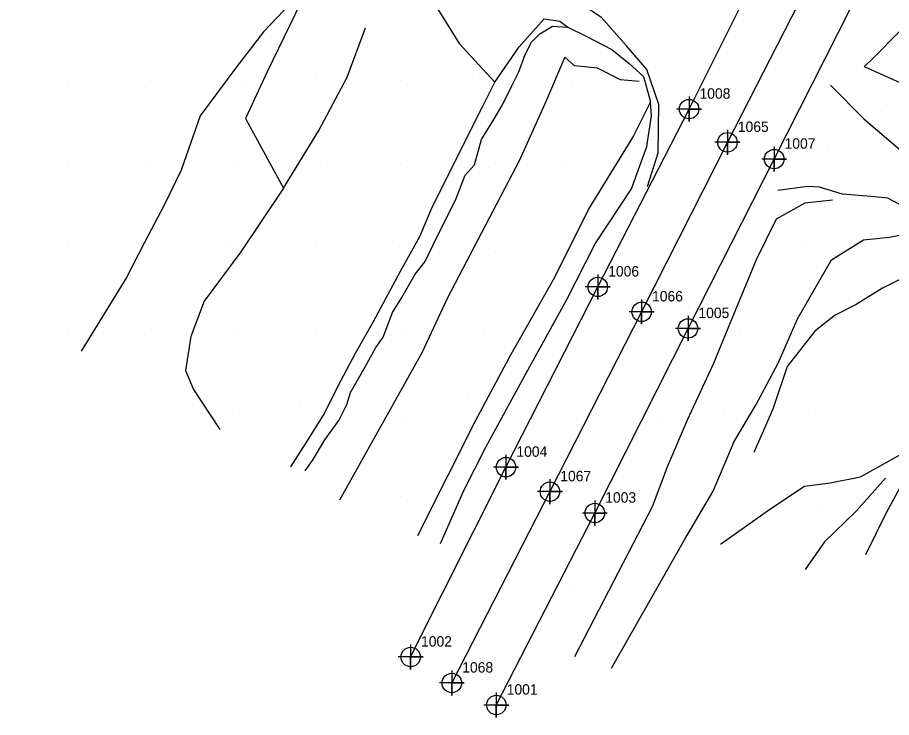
# Model space of a CAD drawing. Extents: x 2062781 to 2066835, y 358981 to 366501.
# Drawn here: x 2063191.9 to 2063402.2, y 359933.1 to 360101.4 of the extents above; entities that cross this region are included whole.
import ezdxf

# ---------------------------------------------------------------- set-up
doc = ezdxf.new("R2010")
doc.units = 0
for name, color, linetype in [('Exist DTM Crownline', 7, 'Continuous'), ('Exist DTM Crownline Cogo Number', 7, 'Continuous'), ('Exist DTM Crownline Cogo Point CELL', 7, 'Continuous'), ('Exist Roads EOP', 7, 'Continuous'), ('Exist Roads EOP Cogo Number', 7, 'Continuous'), ('Exist Roads EOP Cogo Point CELL', 7, 'Continuous'), ('PH Exist DTM Breakline', 7, 'Continuous'), ('PH Exist DTM Point', 7, 'Continuous')]:
    doc.layers.add(name, color=color, linetype=linetype)

msp = doc.modelspace()

# ---------------------------------------------------------------- linework, layer by layer
at = {"layer": 'Exist DTM Crownline'}
msp.add_lwpolyline([(2063750.55, 360833.69), (2063727.84, 360789.3), (2063705.93, 360746.41), (2063683.92, 360702.88), (2063663.24, 360662.2), (2063641.44, 360619.31), (2063619.27, 360575.63), (2063598.51, 360534.74), (2063576.26, 360491.01), (2063554.11, 360448.07), (2063531.69, 360403.69), (2063510.6, 360362.17), (2063489.74, 360321.58), (2063468.62, 360279.83), (2063447.14, 360237.46), (2063426.34, 360196.56), (2063406.83, 360158.2), (2063384.9, 360114.87), (2063362.69, 360071.39), (2063342.05, 360030.63), (2063319.97, 359987.39), (2063296.38, 359941.39)], dxfattribs=at)
at = {"layer": 'Exist DTM Crownline Cogo Point CELL'}
for points in [[(2063362.69, 360074.39), (2063362.69, 360068.39), (2063362.69, 360071.39), (2063365.69, 360071.39), (2063359.69, 360071.39)], [(2063362.69, 360074.39), (2063362.69, 360068.39), (2063362.69, 360071.39), (2063365.69, 360071.39), (2063359.69, 360071.39)], [(2063362.69, 360074.39), (2063362.69, 360068.39), (2063362.69, 360071.39), (2063365.69, 360071.39), (2063359.69, 360071.39)], [(2063342.05, 360033.63), (2063342.05, 360027.63), (2063342.05, 360030.63), (2063345.05, 360030.63), (2063339.05, 360030.63)], [(2063342.05, 360033.63), (2063342.05, 360027.63), (2063342.05, 360030.63), (2063345.05, 360030.63), (2063339.05, 360030.63)], [(2063342.05, 360033.63), (2063342.05, 360027.63), (2063342.05, 360030.63), (2063345.05, 360030.63), (2063339.05, 360030.63)], [(2063319.97, 359990.39), (2063319.97, 359984.39), (2063319.97, 359987.39), (2063322.97, 359987.39), (2063316.97, 359987.39)], [(2063319.97, 359990.39), (2063319.97, 359984.39), (2063319.97, 359987.39), (2063322.97, 359987.39), (2063316.97, 359987.39)], [(2063319.97, 359990.39), (2063319.97, 359984.39), (2063319.97, 359987.39), (2063322.97, 359987.39), (2063316.97, 359987.39)], [(2063296.38, 359944.39), (2063296.38, 359938.39), (2063296.38, 359941.39), (2063299.38, 359941.39), (2063293.38, 359941.39)], [(2063296.38, 359944.39), (2063296.38, 359938.39), (2063296.38, 359941.39), (2063299.38, 359941.39), (2063293.38, 359941.39)], [(2063296.38, 359944.39), (2063296.38, 359938.39), (2063296.38, 359941.39), (2063299.38, 359941.39), (2063293.38, 359941.39)]]:
    msp.add_lwpolyline(points, dxfattribs=at)
for centre in [(2063362.69, 360071.39), (2063362.69, 360071.39), (2063362.69, 360071.39), (2063342.05, 360030.63), (2063342.05, 360030.63), (2063342.05, 360030.63), (2063319.97, 359987.39), (2063319.97, 359987.39), (2063319.97, 359987.39), (2063296.38, 359941.39), (2063296.38, 359941.39), (2063296.38, 359941.39)]:
    msp.add_circle(centre, 2.34, dxfattribs=at)
at = {"layer": 'Exist Roads EOP'}
for points in [[(2063286.47, 359947.64), (2063309.41, 359993.28), (2063331.5, 360036.62), (2063353.47, 360079.37), (2063374.09, 360120.61), (2063394.89, 360165.38), (2063417.4, 360208.71), (2063436.23, 360246.03), (2063449.27, 360270.89), (2063451.38, 360272.28), (2063457.84, 360285.06), (2063479.58, 360327.99), (2063500.63, 360369.12), (2063521.45, 360410.21), (2063543.5, 360453.45), (2063565.77, 360497.25), (2063587.25, 360539.79), (2063609.2, 360582.5), (2063630.76, 360625.39), (2063652.41, 360668.3), (2063674.4, 360710.54), (2063695.41, 360752.05), (2063717.28, 360794.95), (2063739.23, 360837.72)], [(2063307.08, 359936.09), (2063330.79, 359982.25), (2063353.21, 360026.63), (2063373.94, 360067.35), (2063395.33, 360109.66), (2063417.3, 360152.86), (2063438.53, 360194.57), (2063458.78, 360234.01), (2063479.37, 360275.02), (2063500.83, 360316.36), (2063521.71, 360358), (2063542.56, 360398.65), (2063564.98, 360442.66), (2063586.95, 360486.19), (2063608.7, 360528.89), (2063630.33, 360571.32), (2063652.02, 360613.69), (2063674.28, 360656.66), (2063695.45, 360699.25), (2063716.63, 360740.88), (2063738.76, 360783.94), (2063760.61, 360827.22)]]:
    msp.add_lwpolyline(points, dxfattribs=at)
at = {"layer": 'Exist Roads EOP Cogo Point CELL'}
for points in [[(2063353.47, 360082.37), (2063353.47, 360076.37), (2063353.47, 360079.37), (2063356.47, 360079.37), (2063350.47, 360079.37)], [(2063353.47, 360082.37), (2063353.47, 360076.37), (2063353.47, 360079.37), (2063356.47, 360079.37), (2063350.47, 360079.37)], [(2063353.47, 360082.37), (2063353.47, 360076.37), (2063353.47, 360079.37), (2063356.47, 360079.37), (2063350.47, 360079.37)], [(2063373.94, 360070.35), (2063373.94, 360064.35), (2063373.94, 360067.35), (2063376.94, 360067.35), (2063370.94, 360067.35)], [(2063373.94, 360070.35), (2063373.94, 360064.35), (2063373.94, 360067.35), (2063376.94, 360067.35), (2063370.94, 360067.35)], [(2063373.94, 360070.35), (2063373.94, 360064.35), (2063373.94, 360067.35), (2063376.94, 360067.35), (2063370.94, 360067.35)], [(2063331.5, 360039.62), (2063331.5, 360033.62), (2063331.5, 360036.62), (2063334.5, 360036.62), (2063328.5, 360036.62)], [(2063331.5, 360039.62), (2063331.5, 360033.62), (2063331.5, 360036.62), (2063334.5, 360036.62), (2063328.5, 360036.62)], [(2063331.5, 360039.62), (2063331.5, 360033.62), (2063331.5, 360036.62), (2063334.5, 360036.62), (2063328.5, 360036.62)], [(2063353.21, 360029.63), (2063353.21, 360023.63), (2063353.21, 360026.63), (2063356.21, 360026.63), (2063350.21, 360026.63)], [(2063353.21, 360029.63), (2063353.21, 360023.63), (2063353.21, 360026.63), (2063356.21, 360026.63), (2063350.21, 360026.63)], [(2063353.21, 360029.63), (2063353.21, 360023.63), (2063353.21, 360026.63), (2063356.21, 360026.63), (2063350.21, 360026.63)], [(2063309.41, 359996.28), (2063309.41, 359990.28), (2063309.41, 359993.28), (2063312.41, 359993.28), (2063306.41, 359993.28)], [(2063309.41, 359996.28), (2063309.41, 359990.28), (2063309.41, 359993.28), (2063312.41, 359993.28), (2063306.41, 359993.28)], [(2063309.41, 359996.28), (2063309.41, 359990.28), (2063309.41, 359993.28), (2063312.41, 359993.28), (2063306.41, 359993.28)], [(2063330.79, 359985.25), (2063330.79, 359979.25), (2063330.79, 359982.25), (2063333.79, 359982.25), (2063327.79, 359982.25)], [(2063330.79, 359985.25), (2063330.79, 359979.25), (2063330.79, 359982.25), (2063333.79, 359982.25), (2063327.79, 359982.25)], [(2063330.79, 359985.25), (2063330.79, 359979.25), (2063330.79, 359982.25), (2063333.79, 359982.25), (2063327.79, 359982.25)], [(2063286.47, 359950.64), (2063286.47, 359944.64), (2063286.47, 359947.64), (2063289.47, 359947.64), (2063283.47, 359947.64)], [(2063286.47, 359950.64), (2063286.47, 359944.64), (2063286.47, 359947.64), (2063289.47, 359947.64), (2063283.47, 359947.64)], [(2063286.47, 359950.64), (2063286.47, 359944.64), (2063286.47, 359947.64), (2063289.47, 359947.64), (2063283.47, 359947.64)], [(2063307.08, 359939.09), (2063307.08, 359933.09), (2063307.08, 359936.09), (2063310.08, 359936.09), (2063304.08, 359936.09)], [(2063307.08, 359939.09), (2063307.08, 359933.09), (2063307.08, 359936.09), (2063310.08, 359936.09), (2063304.08, 359936.09)], [(2063307.08, 359939.09), (2063307.08, 359933.09), (2063307.08, 359936.09), (2063310.08, 359936.09), (2063304.08, 359936.09)]]:
    msp.add_lwpolyline(points, dxfattribs=at)
for centre in [(2063353.47, 360079.37), (2063353.47, 360079.37), (2063353.47, 360079.37), (2063373.94, 360067.35), (2063373.94, 360067.35), (2063373.94, 360067.35), (2063331.5, 360036.62), (2063331.5, 360036.62), (2063331.5, 360036.62), (2063353.21, 360026.63), (2063353.21, 360026.63), (2063353.21, 360026.63), (2063309.41, 359993.28), (2063309.41, 359993.28), (2063309.41, 359993.28), (2063330.79, 359982.25), (2063330.79, 359982.25), (2063330.79, 359982.25), (2063286.47, 359947.64), (2063286.47, 359947.64), (2063286.47, 359947.64), (2063307.08, 359936.09), (2063307.08, 359936.09), (2063307.08, 359936.09)]:
    msp.add_circle(centre, 2.34, dxfattribs=at)
at = {"layer": 'PH Exist DTM Breakline'}
for points in [[(2063519.4, 360266.45), (2063512.25, 360275.25), (2063507.51, 360283.25), (2063503.54, 360285.24), (2063498.8, 360285.56), (2063492.85, 360277.94), (2063485.77, 360263.8), (2063477.25, 360243.88), (2063465.7, 360220.43), (2063453.32, 360194.54), (2063442.94, 360174.71), (2063436.49, 360161.61), (2063428.8, 360146.36), (2063421.29, 360131.65), (2063414.03, 360117.16), (2063404.68, 360098.63), (2063397.22, 360091.02), (2063395.56, 360089.61), (2063405.09, 360085.33), (2063410.62, 360089.46), (2063414.8, 360093.7), (2063418.41, 360099.45)], [(2063343.47, 360060.73), (2063346.03, 360068.82), (2063346.2, 360080.46), (2063343.32, 360088.89), (2063338.4, 360094.58), (2063332.37, 360101.42), (2063325.62, 360105.92), (2063317.77, 360110.18), (2063307.13, 360115.51), (2063295.27, 360120.38), (2063278.26, 360128.98), (2063267.35, 360135.54), (2063255.26, 360141.4), (2063237.53, 360147.25), (2063225.92, 360151.37), (2063211.39, 360159.06), (2063195.65, 360167.32), (2063178.83, 360175.76), (2063166.32, 360182.59), (2063150.91, 360191.03), (2063136.88, 360198.06), (2063121.11, 360205.8)], [(2063190.72, 360155.87), (2063195.96, 360153.49), (2063203.12, 360149.81), (2063212.26, 360144.4), (2063222.26, 360139.38), (2063231.63, 360133.97), (2063242.03, 360128.63), (2063252.11, 360122.12), (2063259.12, 360117.49), (2063259.63, 360109.94), (2063256.05, 360103.12), (2063251.05, 360097.95), (2063244.37, 360089.26), (2063235.81, 360077.73), (2063231.21, 360064.65), (2063227.25, 360056.41), (2063222.4, 360047.28), (2063218.09, 360038.87), (2063207.21, 360021.14)], [(2063271.17, 360131.08), (2063268.32, 360125.92), (2063263.86, 360112.72), (2063260.1, 360105.2), (2063251.92, 360088.31), (2063246.76, 360077.09), (2063255.86, 360060.39), (2063245.58, 360045.02), (2063236.79, 360033.22), (2063233.57, 360024.69), (2063232.26, 360016.54), (2063234.22, 360011.98), (2063240.57, 360002.3)], [(2063271.17, 360131.08), (2063277.76, 360124.92), (2063287.9, 360111.77), (2063298.11, 360095.12), (2063306.7, 360085.87)], [(2063257.64, 359993.39), (2063262.25, 360000.66), (2063265.72, 360006.17), (2063269.06, 360012.83), (2063273.18, 360020.68), (2063277.56, 360028.28), (2063284.04, 360040.37), (2063288.69, 360048.74), (2063291.47, 360055.36), (2063296.92, 360066.34), (2063303.89, 360080.26), (2063306.7, 360085.87), (2063312.6, 360094.34), (2063318.59, 360101.11), (2063322.39, 360100.53), (2063324.26, 360099.06)], [(2063255.86, 360060.39), (2063264.41, 360074.2), (2063271.22, 360087.08), (2063275.62, 360098.91)], [(2063261.08, 359992.43), (2063262.82, 359994.92), (2063265.78, 359999.89), (2063269.22, 360004.5), (2063271.14, 360008.35), (2063271.99, 360011.27), (2063275.52, 360017.39), (2063278.06, 360022.07), (2063279.83, 360024.54), (2063282.11, 360030.49), (2063284.33, 360034.06), (2063287.55, 360039.66), (2063290, 360042.74), (2063292.91, 360048.88), (2063297.23, 360057.45), (2063299.55, 360063.46), (2063301.82, 360065.96), (2063303.53, 360072.06), (2063306.47, 360076.89), (2063308.63, 360080.58), (2063310.83, 360084.97), (2063312.52, 360088.35), (2063314.04, 360092.53), (2063315.54, 360095.43), (2063317.58, 360097.5), (2063320.61, 360099.35), (2063324.26, 360099.06), (2063328.84, 360096.8), (2063334.87, 360093.69), (2063339.05, 360090.3), (2063342.51, 360087.24), (2063344.16, 360081.15), (2063340.12, 360072.94), (2063329.38, 360055.46), (2063321.09, 360038.9), (2063310.16, 360019.68), (2063301.93, 360004.18), (2063295.34, 359991.13), (2063288.13, 359976.76)], [(2063341.45, 360086.04), (2063336.93, 360086.42), (2063331.39, 360089.25), (2063325.89, 360089.81), (2063323.56, 360091.86), (2063318.85, 360080.77), (2063312.69, 360067.1), (2063295.35, 360033.97), (2063289.14, 360020.73), (2063269.37, 359985.31)], [(2063387.46, 360085.16), (2063395.51, 360077.05), (2063404.85, 360069.08), (2063414.32, 360061.63), (2063421.42, 360057.31), (2063428.38, 360053.84), (2063440.21, 360050.1), (2063444.7, 360048.23), (2063448.98, 360043.11), (2063454.51, 360037.68), (2063464.09, 360033.39), (2063468.09, 360035.44), (2063473.8, 360041.3), (2063479.07, 360046.6), (2063488.6, 360048.28), (2063500.91, 360046.4), (2063518.19, 360037.75), (2063535.86, 360027.13)], [(2063293.64, 359974.89), (2063299.26, 359987.65), (2063304.56, 359998.1), (2063314.28, 360015.88), (2063324.05, 360033.63), (2063330.87, 360047), (2063339.59, 360060.22), (2063343.32, 360070.4), (2063344.42, 360077.72), (2063344.16, 360081.15)], [(2063409.86, 360053.35), (2063401.31, 360057.92), (2063397.3, 360058.36), (2063390.35, 360058.9), (2063384.83, 360060.6), (2063381.93, 360060.74), (2063374.79, 360059.8)], [(2063387.95, 360057.45), (2063381.34, 360056.72), (2063374.4, 360052.93), (2063369.59, 360043.14), (2063364.66, 360031.09), (2063359.23, 360018.01), (2063352.97, 360004.59), (2063348.28, 359993.49), (2063344.62, 359983.73), (2063325.93, 359947.71)], [(2063334.83, 359944.99), (2063352.34, 359975.83), (2063359.29, 359987.48), (2063364.34, 359999.43), (2063369.62, 360008.34), (2063374.92, 360018.31), (2063379.53, 360028.98), (2063387.75, 360043.17), (2063395.47, 360047.95), (2063401.72, 360048.59), (2063410.18, 360050.3), (2063416.8, 360045.97), (2063420.12, 360041.73), (2063421.9, 360037.66)], [(2063423.96, 360044.44), (2063426.36, 360039.1), (2063424.63, 360035.28), (2063420.93, 360033.56), (2063416.7, 360035.83), (2063412.89, 360041.62), (2063408.86, 360040.72), (2063400.02, 360036.33), (2063393.69, 360032.38), (2063388.58, 360029.82), (2063383.74, 360026), (2063377.1, 360017.47), (2063373.61, 360007.19), (2063369.03, 359996.83)], [(2063361.05, 359974.76), (2063373.1, 359983.33), (2063381.24, 359988.69), (2063387.45, 359989.52), (2063394.68, 359990.93), (2063404.53, 359996.4), (2063411.01, 360001.48), (2063407, 359993.48), (2063400.92, 359982.3), (2063395.92, 359972.21)], [(2063400.76, 359990.62), (2063393.64, 359982.73), (2063386.07, 359975.29), (2063381.42, 359968.68)]]:
    msp.add_lwpolyline(points, dxfattribs=at)
at = {"layer": 'PH Exist DTM Point'}
for p, q in [((2063203.92, 360086.29), (2063203.92, 360086.29)), ((2063223.92, 360086.31), (2063223.92, 360086.31)), ((2063263.79, 360087.28), (2063263.79, 360087.28)), ((2063283.92, 360086.29), (2063283.92, 360086.29)), ((2063301.26, 360086.87), (2063301.26, 360086.87)), ((2063246.62, 360084.7), (2063246.62, 360084.7)), ((2063325.1, 360085.69), (2063325.1, 360085.69)), ((2063401, 360080.44), (2063401, 360080.44)), ((2063386.86, 360070.19), (2063386.86, 360070.19)), ((2063203.92, 360066.29), (2063203.92, 360066.29)), ((2063223.92, 360066.29), (2063223.92, 360066.29)), ((2063243.92, 360066.29), (2063243.92, 360066.29)), ((2063264.76, 360065.93), (2063264.76, 360065.93)), ((2063283.94, 360066.28), (2063283.94, 360066.28)), ((2063305.22, 360065.24), (2063305.22, 360065.24)), ((2063323.92, 360066.29), (2063323.92, 360066.29)), ((2063203.92, 360046.29), (2063203.92, 360046.29)), ((2063241.91, 360047.59), (2063241.91, 360047.59)), ((2063263.93, 360046.33), (2063263.93, 360046.33)), ((2063283.9, 360046.33), (2063283.9, 360046.33)), ((2063381.53, 360047.48), (2063381.53, 360047.48)), ((2063306.94, 360045.13), (2063306.94, 360045.13)), ((2063203.93, 360026.32), (2063203.93, 360026.32)), ((2063224.04, 360026.32), (2063224.04, 360026.32)), ((2063243.92, 360026.29), (2063243.92, 360026.29)), ((2063263.92, 360026.3), (2063263.92, 360026.3)), ((2063284.15, 360026.17), (2063284.15, 360026.17)), ((2063303.93, 360026.32), (2063303.93, 360026.32)), ((2063365.76, 360025.3), (2063365.76, 360025.3)), ((2063259.74, 360008.91), (2063259.74, 360008.91)), ((2063300.39, 360009.92), (2063300.39, 360009.92)), ((2063362.02, 360007.23), (2063362.02, 360007.23)), ((2063383.92, 360006.29), (2063383.92, 360006.29)), ((2063243.65, 360006.16), (2063243.65, 360006.16)), ((2063285.13, 360005.41), (2063285.13, 360005.41)), ((2063347.15, 360004.67), (2063347.15, 360004.67)), ((2063341.54, 359987.56), (2063341.54, 359987.56)), ((2063283.92, 359986.29), (2063283.92, 359986.29)), ((2063384.61, 359984.1), (2063384.61, 359984.1)), ((2063325.91, 359964.08), (2063325.91, 359964.08))]:
    msp.add_line(p, q, dxfattribs=at)

# ---------------------------------------------------------------- texts
at = {"layer": 'Exist DTM Crownline Cogo Number'}
for s, p in [('1065', (2063365.19, 360073.89)), ('1065', (2063365.19, 360073.89)), ('1065', (2063365.19, 360073.89)), ('1066', (2063344.55, 360033.13)), ('1066', (2063344.55, 360033.13)), ('1066', (2063344.55, 360033.13)), ('1067', (2063322.47, 359989.89)), ('1067', (2063322.47, 359989.89)), ('1067', (2063322.47, 359989.89)), ('1068', (2063298.88, 359943.89)), ('1068', (2063298.88, 359943.89)), ('1068', (2063298.88, 359943.89))]:
    msp.add_text(s, height=2.5, dxfattribs=at).set_placement(p)
at = {"layer": 'Exist Roads EOP Cogo Number'}
for s, p in [('1008', (2063355.97, 360081.87)), ('1008', (2063355.97, 360081.87)), ('1008', (2063355.97, 360081.87)), ('1007', (2063376.44, 360069.85)), ('1007', (2063376.44, 360069.85)), ('1007', (2063376.44, 360069.85)), ('1006', (2063334, 360039.12)), ('1006', (2063334, 360039.12)), ('1006', (2063334, 360039.12)), ('1005', (2063355.71, 360029.13)), ('1005', (2063355.71, 360029.13)), ('1005', (2063355.71, 360029.13)), ('1004', (2063311.91, 359995.78)), ('1004', (2063311.91, 359995.78)), ('1004', (2063311.91, 359995.78)), ('1003', (2063333.29, 359984.75)), ('1003', (2063333.29, 359984.75)), ('1003', (2063333.29, 359984.75)), ('1002', (2063288.97, 359950.14)), ('1002', (2063288.97, 359950.14)), ('1002', (2063288.97, 359950.14)), ('1001', (2063309.58, 359938.59)), ('1001', (2063309.58, 359938.59)), ('1001', (2063309.58, 359938.59))]:
    msp.add_text(s, height=2.5, dxfattribs=at).set_placement(p)

doc.saveas('drawing.dxf')
